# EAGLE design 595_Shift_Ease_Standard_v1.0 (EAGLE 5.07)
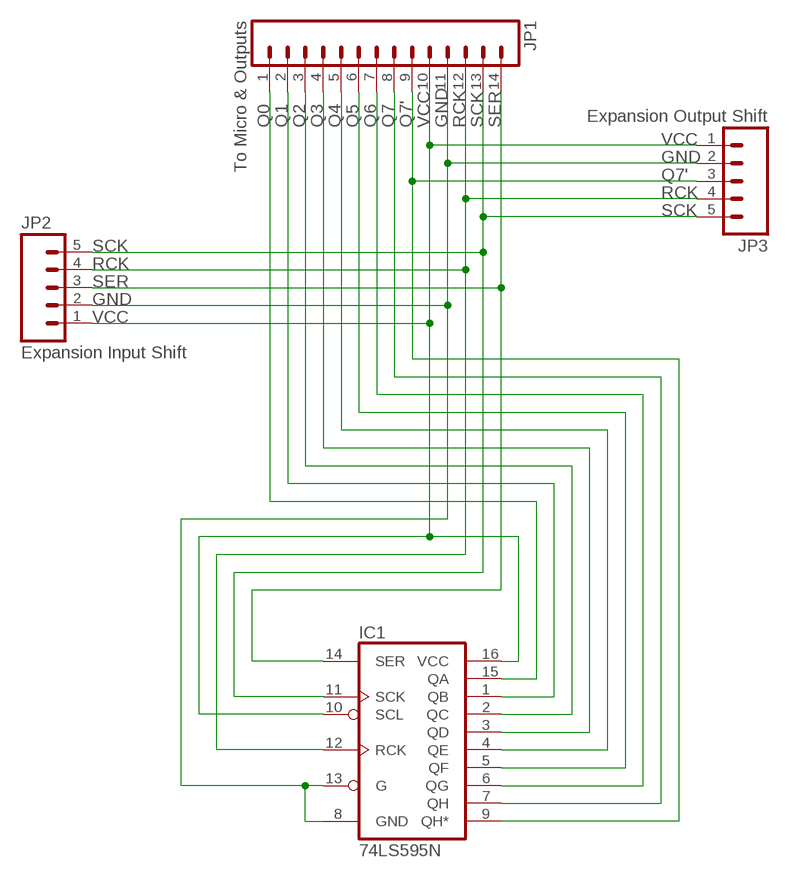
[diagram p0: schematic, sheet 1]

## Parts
IC1  74LS595N  [DIL16]
JP1  To Micro & Outputs  M141X14_FH  [1X14_FH]
JP2  Expansion Input Shift  M051X05_M_H  [1X05_M_H]
JP3  Expansion Output Shift  M051X05_F_H  [1X05_F_H]

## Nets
GND: IC1.8(GND) IC1.13(G) JP1.11 JP2.2 JP3.2
Q0: IC1.15(QA) JP1.1
Q1: IC1.1(QB) JP1.2
Q2: IC1.2(QC) JP1.3
Q3: IC1.3(QD) JP1.4
Q4: IC1.4(QE) JP1.5
Q5: IC1.5(QF) JP1.6
Q6: IC1.6(QG) JP1.7
Q7: IC1.7(QH) JP1.8
Q7': IC1.9(QH*) JP1.9 JP3.3
RCK: IC1.12(RCK) JP1.12 JP2.4 JP3.4
SCK: IC1.11(SCK) JP1.13 JP2.5 JP3.5
SER: IC1.14(SER) JP1.14 JP2.3
VCC: IC1.10(SCL) IC1.16(VCC) JP1.10 JP2.1 JP3.1

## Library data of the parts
IC1 = SparkFun:74*595: 8-bit SHIFT REGISTER, output latch
JP1 = SparkFun:M14: Header 14 Standard 14-pin 0.1" header. Use with straight break away headers (SKU : PRT-00116), right angle break away headers (PRT-00553), swiss pins (PRT-00743), machine pins (PRT-00117), and female headers (PRT-00115).
JP2 JP3 = SparkFun:M05: Header 5 Standard 5-pin 0.1" header. Use with straight break away headers (SKU : PRT-00116), right angle break away headers (PRT-00553), swiss pins (PRT-00743), machine pins (PRT-00117), and female headers (PRT-00115). Molex polarized connector foot print use with SKU : PRT-08230 with associated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

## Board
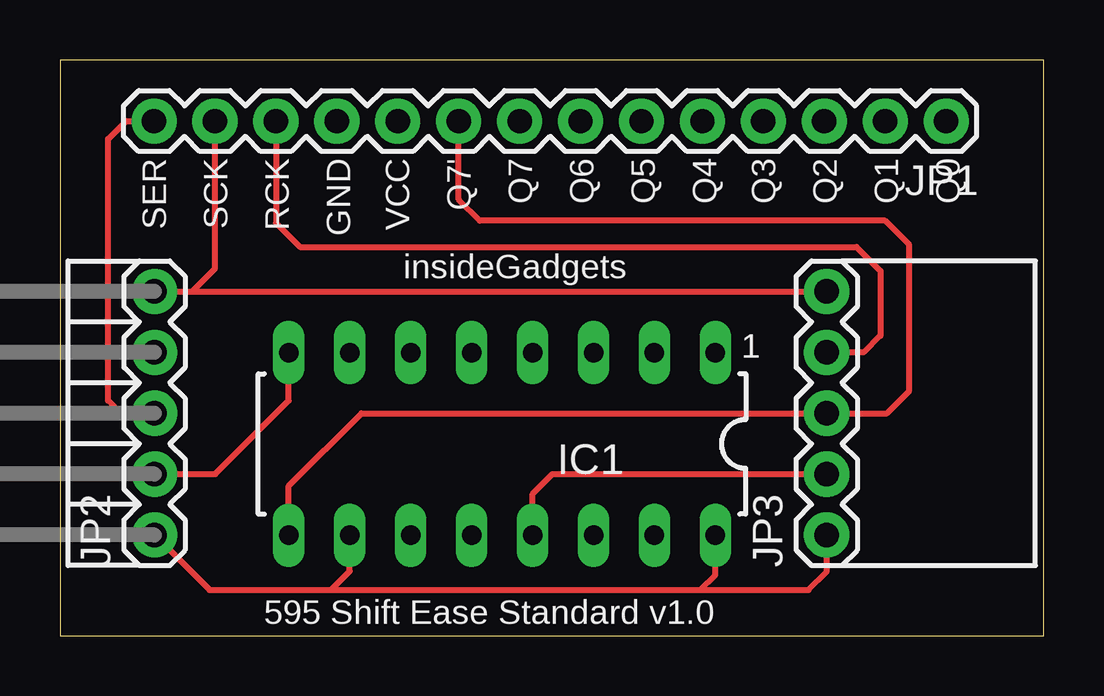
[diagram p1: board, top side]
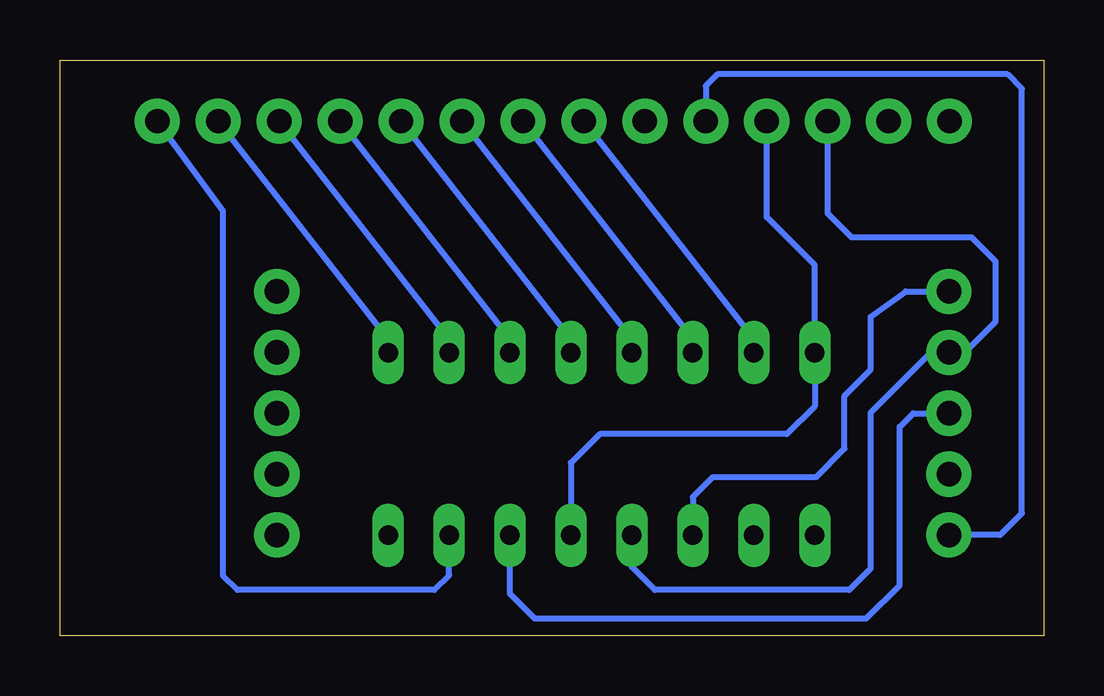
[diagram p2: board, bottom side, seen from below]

Size 41 x 24 mm. Coordinates in mm from the lower left corner, seen from the top.
Outline: 0,0 41,0 41,24 0,24 0,0
Copper layers (1*16): Top 0.035mm / dielectric 1.5mm / Bottom 0.035mm
Design rules "ITead_rule": minimum track width 6mil, minimum drill 12mil, track to track 6mil, track to pad 6mil, pad to pad 6mil, via to via 6mil, smd to smd 0mil, copper to edge 10mil, drill to drill 10mil, minimum pad ring 10mil, minimum via ring 6mil, stop-mask expansion 2mil, vias tented up to drill 100mil, thermal gap 10mil

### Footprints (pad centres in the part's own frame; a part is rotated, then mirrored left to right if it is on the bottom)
DIL16 = drill 0.813 long: 1 -8.89,-3.81; 2 -6.35,-3.81; 3 -3.81,-3.81; 4 -1.27,-3.81; 5 1.27,-3.81; 6 3.81,-3.81; 7 6.35,-3.81; 8 8.89,-3.81; 9 8.89,3.81; 10 6.35,3.81; 11 3.81,3.81; 12 1.27,3.81; 13 -1.27,3.81; 14 -3.81,3.81; 15 -6.35,3.81; 16 -8.89,3.81
1X14_FH = drill 1.016 pad 1.88 round: 1 0,0; 2 2.54,0; 3 5.08,0; 4 7.62,0; 5 10.16,0; 6 12.7,0; 7 15.24,0; 8 17.78,0; 9 20.32,0; 10 22.86,0; 11 25.4,0; 12 27.94,0; 13 30.48,0; 14 33.02,0
1X05_M_H = drill 1.016 pad 1.88 round: 1 0,0; 2 2.54,0; 3 5.08,0; 4 7.62,0; 5 10.16,0
1X05_F_H = drill 1.016 pad 1.88 round: 1 0,0; 2 2.54,0; 3 5.08,0; 4 7.62,0; 5 10.16,0

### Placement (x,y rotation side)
IC1  18.43,7.99 180 top
JP1  36.94,21.45 180 top
JP2  3.94,4.19 90 top
JP3  31.96,4.19 90 top

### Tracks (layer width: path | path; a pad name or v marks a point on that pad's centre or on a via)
GND
  Top 0.254: JP2.2 6.47,6.73 9.54,9.8 IC1.8 | IC1.13 19.7,5.9 20.53,6.73 JP3.2
  Bottom 0.254: JP1.11 11.54,17.44 9.54,15.44 IC1.8 9.54,9.56 10.7,8.4 18.5,8.4 19.7,7.2 IC1.13
Q0
  Bottom 0.254: IC1.15 24.78,2.52 25.4,1.9 33.6,1.9 34.2,2.5 34.2,17.7 JP1.1
Q1
  Bottom 0.254: JP1.2 27.32,12.37 IC1.1
Q2
  Bottom 0.254: JP1.3 24.78,12.37 IC1.2
Q3
  Bottom 0.254: JP1.4 22.24,12.37 IC1.3
Q4
  Bottom 0.254: JP1.5 19.7,12.37 IC1.4
Q5
  Bottom 0.254: JP1.6 17.16,12.37 IC1.5
Q6
  Bottom 0.254: JP1.7 14.62,12.37 IC1.6
Q7
  Bottom 0.254: JP1.8 12.08,12.37 IC1.7
Q7'
  Top 0.254: JP1.9 16.62,18.18 17.5,17.3 34.4,17.3 35.4,16.3 35.4,10.2 34.47,9.27 JP3.3 12.57,9.27 9.54,6.24 IC1.9
RCK
  Top 0.254: JP1.12 9,17.2 10,16.2 33.2,16.2 34.2,15.2 34.2,12.5 33.51,11.81 JP3.4
  Bottom 0.254: JP1.12 9,17.6 8,16.6 3,16.6 2,15.6 2,13.1 3.29,11.81 JP2.4 4.69,11.81 7.2,9.3 7.2,2.8 8.1,1.9 16.2,1.9 17.16,2.86 IC1.12
SCK
  Top 0.254: JP2.5 5.5,14.35 | 5.5,14.35 JP3.5 | JP1.13 6.46,15.31 5.5,14.35
  Bottom 0.254: JP2.5 5.75,14.35 7.2,13.3 7.2,11.1 8.3,10 8.3,7.8 9.5,6.6 13.8,6.6 14.62,5.78 IC1.11
SER
  Top 0.254: JP2.3 2.53,9.27 2,9.8 2,20.7 2.75,21.45 JP1.14
  Bottom 0.254: JP2.3 5.43,9.27 6,8.7 6,2.1 7.4,0.7 21.2,0.7 22.24,1.74 IC1.14
VCC
  Top 0.254: JP2.1 6.23,1.9 11.3,1.9 | 11.3,1.9 26.7,1.9 | 26.7,1.9 31.2,1.9 31.96,2.66 JP3.1 | IC1.10 12.08,2.68 11.3,1.9 | IC1.16 27.32,2.52 26.7,1.9
  Bottom 0.254: JP2.1 1.81,4.19 0.9,5.1 0.9,22.8 1.5,23.4 13.6,23.4 14.08,22.92 JP1.10

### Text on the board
tPlace: SER | SCK | RCK | GND | VCC | Q7' | Q7 | Q6 | Q5 | Q4 | Q3 | Q2 | Q1 | Q0 | insideGadgets | 1 | 595 Shift Ease Standard v1.0
tValues: SCK | SCK | RCK | RCK | SER | Q7' | GND | GND | VCC | VCC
